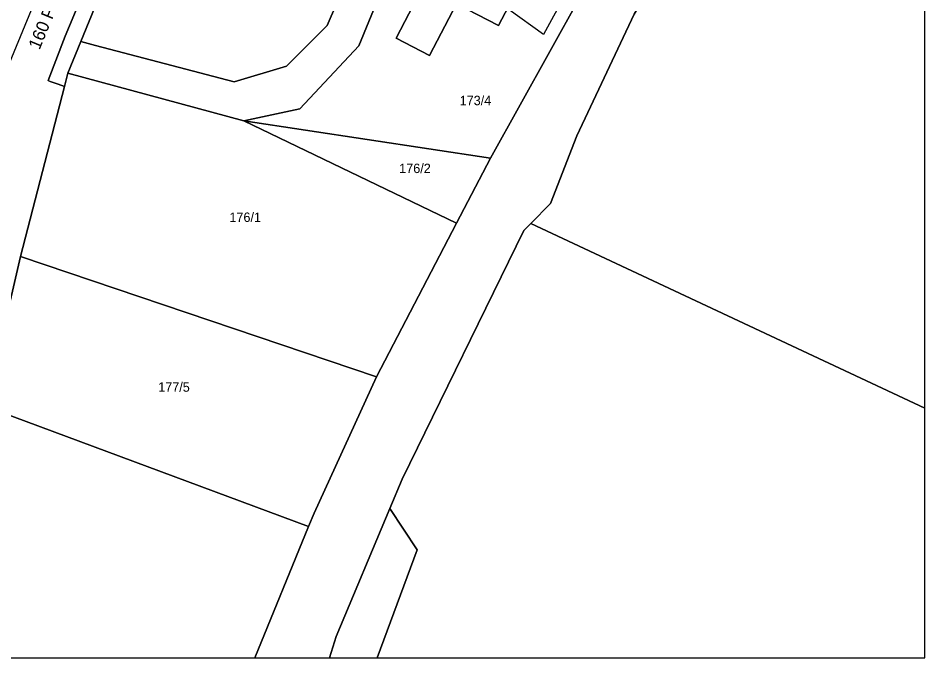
# Model space of a CAD drawing. Extents: x -559956 to -559707, y -1077221 to -1076919.
# Drawn here: x -559851.2 to -559707, y -1077221.3 to -1077119.6 of the extents above; entities that cross this region are included whole.
import ezdxf

# ---------------------------------------------------------------- set-up
doc = ezdxf.new("R2010")
doc.units = 0
for name, color, linetype in [('Parcela-polygon', 7, 'Continuous'), ('Parcela-text', 7, 'Continuous'), ('Vodovodní přípojka', 7, 'Continuous'), ('Vodovodní řad', 7, 'Continuous'), ('Řad vodovodní popis', 7, 'Continuous')]:
    doc.layers.add(name, color=color, linetype=linetype)

msp = doc.modelspace()

# ---------------------------------------------------------------- linework, layer by layer
at = {"layer": 'Parcela-polygon'}
for p, q in [((-559707.02, -1077181.6), (-559707.02, -1077084.04)), ((-559864.4, -1077221.34), (-559813.55, -1077221.34)), ((-559813.55, -1077221.34), (-559801.67, -1077221.34)), ((-559801.67, -1077221.34), (-559794.07, -1077221.34))]:
    msp.add_line(p, q, dxfattribs=at)
for points in [[(-559707.02, -1077024.54), (-559732.09, -1077063.84), (-559737.55, -1077070.66), (-559748, -1077091.24), (-559761.93, -1077116.33), (-559776.08, -1077141.84), (-559781.47, -1077152.19), (-559794.21, -1077176.64), (-559804.13, -1077198.3), (-559804.99, -1077200.42), (-559813.55, -1077221.34)], [(-559801.67, -1077221.34), (-559800.59, -1077217.94), (-559792.07, -1077197.58), (-559790.13, -1077192.93), (-559770.77, -1077153.33), (-559769.65, -1077152.21), (-559766.54, -1077149.07), (-559762.33, -1077138.31), (-559753.22, -1077118.95), (-559733.87, -1077086.69), (-559718.8, -1077083.46), (-559716.92, -1077078.99), (-559715.17, -1077074.8), (-559714.69, -1077073.65), (-559712.93, -1077069.45), (-559713.95, -1077055.83), (-559707.02, -1077045.12)], [(-559707.02, -1077084.04), (-559716.92, -1077078.99), (-559718.8, -1077083.46), (-559733.87, -1077086.69), (-559753.22, -1077118.95), (-559762.33, -1077138.31), (-559766.54, -1077149.07), (-559769.65, -1077152.21), (-559707.02, -1077181.6)], [(-559841.38, -1077116.88), (-559843.69, -1077122.42), (-559846.42, -1077129.5), (-559846.09, -1077129.62), (-559844.82, -1077130.09), (-559843.82, -1077130.46), (-559843.27, -1077128.31), (-559841.22, -1077123.3), (-559834.22, -1077106.14)], [(-559864.4, -1077221.34), (-559862.51, -1077211.37), (-559858.99, -1077192.54), (-559856.37, -1077181.34), (-559850.79, -1077157.5), (-559843.82, -1077130.46), (-559844.82, -1077130.09), (-559846.09, -1077129.62), (-559846.42, -1077129.5), (-559843.69, -1077122.42), (-559841.38, -1077116.88)], [(-559707.02, -1077181.6), (-559769.65, -1077152.21), (-559770.77, -1077153.33), (-559790.13, -1077192.93), (-559792.07, -1077197.58), (-559787.74, -1077204.14), (-559794.07, -1077221.34)], [(-559813.55, -1077221.34), (-559804.99, -1077200.42), (-559856.37, -1077181.34), (-559858.99, -1077192.54), (-559862.51, -1077211.37), (-559864.4, -1077221.34)], [(-559794.07, -1077221.34), (-559707.02, -1077221.34), (-559707.02, -1077181.6)], [(-559794.07, -1077221.34), (-559787.74, -1077204.14), (-559792.07, -1077197.58), (-559800.59, -1077217.94), (-559801.67, -1077221.34)]]:
    msp.add_lwpolyline(points, dxfattribs=at)
for points in [[(-559786.1, -1077097.37), (-559758.48, -1077060.82), (-559763.29, -1077057.42), (-559773.5, -1077072.29), (-559775.27, -1077074.87), (-559785.19, -1077089.31), (-559786.96, -1077091.88), (-559794.15, -1077102.35), (-559802.04, -1077120.75), (-559808.49, -1077127.23), (-559816.84, -1077129.72), (-559838.86, -1077123.92), (-559841.22, -1077123.3), (-559843.27, -1077128.31), (-559815.3, -1077135.92), (-559806.38, -1077134), (-559797.01, -1077123.99), (-559787.45, -1077100.67)], [(-559786.96, -1077091.88), (-559822.49, -1077079.28), (-559825.6, -1077088.11), (-559834.22, -1077106.14), (-559841.22, -1077123.3), (-559838.86, -1077123.92), (-559816.84, -1077129.72), (-559808.49, -1077127.23), (-559802.04, -1077120.75), (-559794.15, -1077102.35)], [(-559766.16, -1077113.76), (-559787.45, -1077100.67), (-559797.01, -1077123.99), (-559806.38, -1077134), (-559815.3, -1077135.92), (-559776.08, -1077141.84), (-559761.93, -1077116.33)], [(-559791.08, -1077122.77), (-559785.75, -1077125.53), (-559781.47, -1077117.31), (-559774.81, -1077120.76), (-559771.59, -1077114.52), (-559783.58, -1077108.34)], [(-559771.59, -1077114.52), (-559774.81, -1077120.76), (-559781.47, -1077117.31), (-559785.75, -1077125.53), (-559791.08, -1077122.77), (-559783.58, -1077108.34)], [(-559843.27, -1077128.31), (-559843.82, -1077130.46), (-559850.79, -1077157.5), (-559794.21, -1077176.64), (-559781.47, -1077152.19), (-559815.3, -1077135.92)], [(-559776.08, -1077141.84), (-559815.3, -1077135.92), (-559781.47, -1077152.19)], [(-559850.79, -1077157.5), (-559856.37, -1077181.34), (-559804.99, -1077200.42), (-559804.13, -1077198.3), (-559794.21, -1077176.64)]]:
    msp.add_lwpolyline(points, close=True, dxfattribs=at)
at = {"layer": 'Vodovodní přípojka'}
msp.add_lwpolyline([(-559812.21, -1077025.22), (-559740.37, -1077063.33), (-559742.92, -1077070.61), (-559742.92, -1077076.8), (-559767.64, -1077122.16), (-559773.1, -1077118.25)], dxfattribs=at)
at = {"layer": 'Vodovodní řad'}
msp.add_lwpolyline([(-559855.58, -1077135.36), (-559854.61, -1077131.63), (-559836.26, -1077087.24), (-559830.32, -1077072.6), (-559827.99, -1077065.05), (-559825.74, -1077057.26), (-559824.33, -1077045.42), (-559823.1, -1077037.32)], dxfattribs=at)

# ---------------------------------------------------------------- texts
at = {"layer": 'Parcela-text'}
for s, p in [('173/4', (-559780.98, -1077133.42)), ('176/2', (-559790.59, -1077144.21)), ('176/1', (-559817.58, -1077151.99)), ('177/5', (-559828.9, -1077179))]:
    msp.add_text(s, height=1.5, dxfattribs=at).set_placement(p)
at = {"layer": 'Řad vodovodní popis'}
msp.add_text(' 160 PVC', height=2, rotation=67.5433, dxfattribs=at).set_placement((-559848.06, -1077125.4))

doc.saveas('drawing.dxf')
